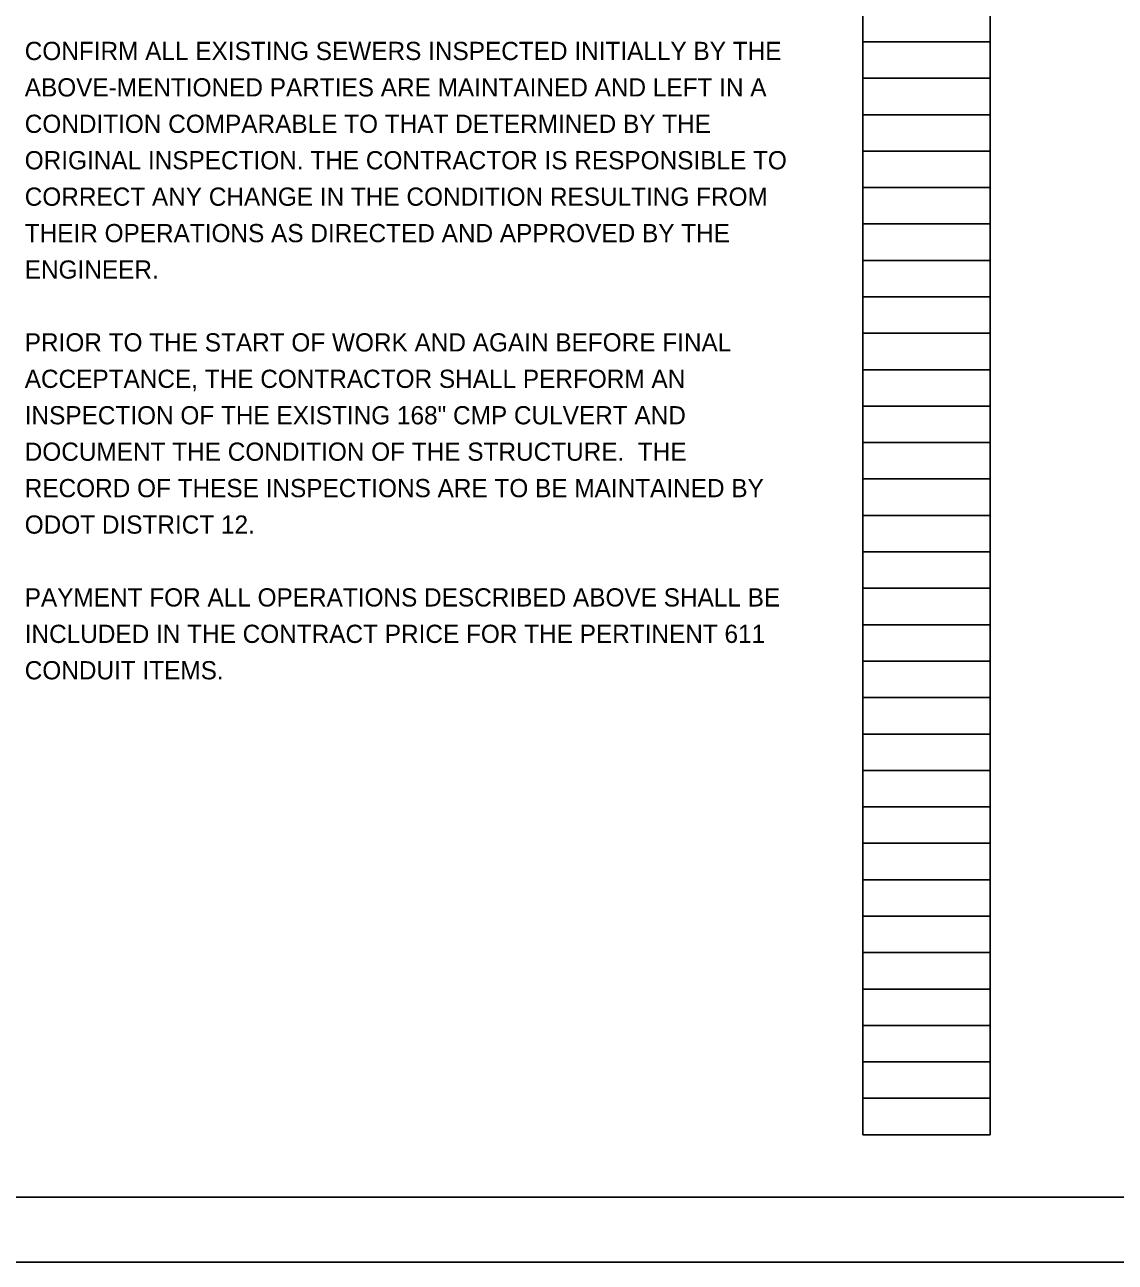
# Model space of a CAD drawing. Extents: x 0 to 34, y 0 to 22.
# Drawn here: x 17.24 to 25.62, y 0 to 9.51 of the extents above; entities that cross this region are included whole.
import ezdxf

# ---------------------------------------------------------------- set-up
doc = ezdxf.new("R2010")
doc.units = 0
for name, color, linetype in [('SH_Border', 7, 'Continuous'), ('SH_Cut_Line', 7, 'Continuous'), ('SH_Data', 7, 'Continuous'), ('SH_Text', 7, 'Continuous')]:
    doc.layers.add(name, color=color, linetype=linetype)

msp = doc.modelspace()

# ---------------------------------------------------------------- linework, layer by layer
at = {"layer": 'SH_Border'}
msp.add_lwpolyline([(1.5, 21.5), (33.5, 21.5), (33.5, 0.5), (1.5, 0.5)], close=True, dxfattribs=at)
at = {"layer": 'SH_Cut_Line'}
msp.add_lwpolyline([(0, 0), (34, 0), (34, 22), (0, 22)], close=True, dxfattribs=at)
at = {"layer": 'SH_Data'}
for p, q in [((23.68, 0.98), (23.68, 21.14)), ((24.66, 0.98), (24.66, 21.14)), ((23.68, 9.38), (24.66, 9.38)), ((23.68, 9.1), (24.66, 9.1)), ((23.68, 8.82), (24.66, 8.82)), ((23.68, 8.54), (24.66, 8.54)), ((23.68, 8.26), (24.66, 8.26)), ((23.68, 7.98), (24.66, 7.98)), ((23.68, 7.7), (24.66, 7.7)), ((23.68, 7.42), (24.66, 7.42)), ((23.68, 7.14), (24.66, 7.14)), ((23.68, 6.86), (24.66, 6.86)), ((23.68, 6.58), (24.66, 6.58)), ((23.68, 6.3), (24.66, 6.3)), ((23.68, 6.02), (24.66, 6.02)), ((23.68, 5.74), (24.66, 5.74)), ((23.68, 5.46), (24.66, 5.46)), ((23.68, 5.18), (24.66, 5.18)), ((23.68, 4.9), (24.66, 4.9)), ((23.68, 4.62), (24.66, 4.62)), ((23.68, 4.34), (24.66, 4.34)), ((23.68, 4.06), (24.66, 4.06)), ((23.68, 3.78), (24.66, 3.78)), ((23.68, 3.5), (24.66, 3.5)), ((23.68, 3.22), (24.66, 3.22)), ((23.68, 2.94), (24.66, 2.94)), ((23.68, 2.66), (24.66, 2.66)), ((23.68, 2.38), (24.66, 2.38)), ((23.68, 2.1), (24.66, 2.1)), ((23.68, 1.82), (24.66, 1.82)), ((23.68, 1.54), (24.66, 1.54)), ((23.68, 1.26), (24.66, 1.26)), ((23.68, 0.98), (24.66, 0.98))]:
    msp.add_line(p, q, dxfattribs=at)

# ---------------------------------------------------------------- texts
at = {"layer": 'SH_Text'}
for s, p in [('CONFIRM ALL EXISTING SEWERS INSPECTED INITIALLY BY THE ', (17.24, 9.24)), ('ABOVE-MENTIONED PARTIES ARE MAINTAINED AND LEFT IN A ', (17.24, 8.96)), ('CONDITION COMPARABLE TO THAT DETERMINED BY THE ', (17.24, 8.68)), ('ORIGINAL INSPECTION. THE CONTRACTOR IS RESPONSIBLE TO', (17.24, 8.4)), ('CORRECT ANY CHANGE IN THE CONDITION RESULTING FROM ', (17.24, 8.12)), ('THEIR OPERATIONS AS DIRECTED AND APPROVED BY THE ', (17.24, 7.84)), ('ENGINEER.', (17.24, 7.56)), ('PRIOR TO THE START OF WORK AND AGAIN BEFORE FINAL ', (17.24, 7)), ('ACCEPTANCE, THE CONTRACTOR SHALL PERFORM AN ', (17.24, 6.72)), ('INSPECTION OF THE EXISTING 168" CMP CULVERT AND ', (17.24, 6.44)), ('DOCUMENT THE CONDITION OF THE STRUCTURE.  THE ', (17.24, 6.16)), ('RECORD OF THESE INSPECTIONS ARE TO BE MAINTAINED BY ', (17.24, 5.88)), ('ODOT DISTRICT 12.', (17.24, 5.6)), ('PAYMENT FOR ALL OPERATIONS DESCRIBED ABOVE SHALL BE ', (17.24, 5.04)), ('INCLUDED IN THE CONTRACT PRICE FOR THE PERTINENT 611 ', (17.24, 4.76)), ('CONDUIT ITEMS.', (17.24, 4.48))]:
    msp.add_text(s, height=0.14, dxfattribs=at).set_placement(p)

doc.saveas('drawing.dxf')
